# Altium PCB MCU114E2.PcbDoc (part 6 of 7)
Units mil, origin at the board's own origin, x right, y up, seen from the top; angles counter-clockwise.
Board outline 4153.94 x 2313.28 mil, 8 copper layers (Top Layer, GND 2, Signal Layer 3, Power 4, Power 5, Signal Layer 6, GND 7, Bottom), stack 61.2 mil thick; 444 components, 418 nets, 1811 pads, 981 vias.
Unrouted connection lines stored in the file: 3.
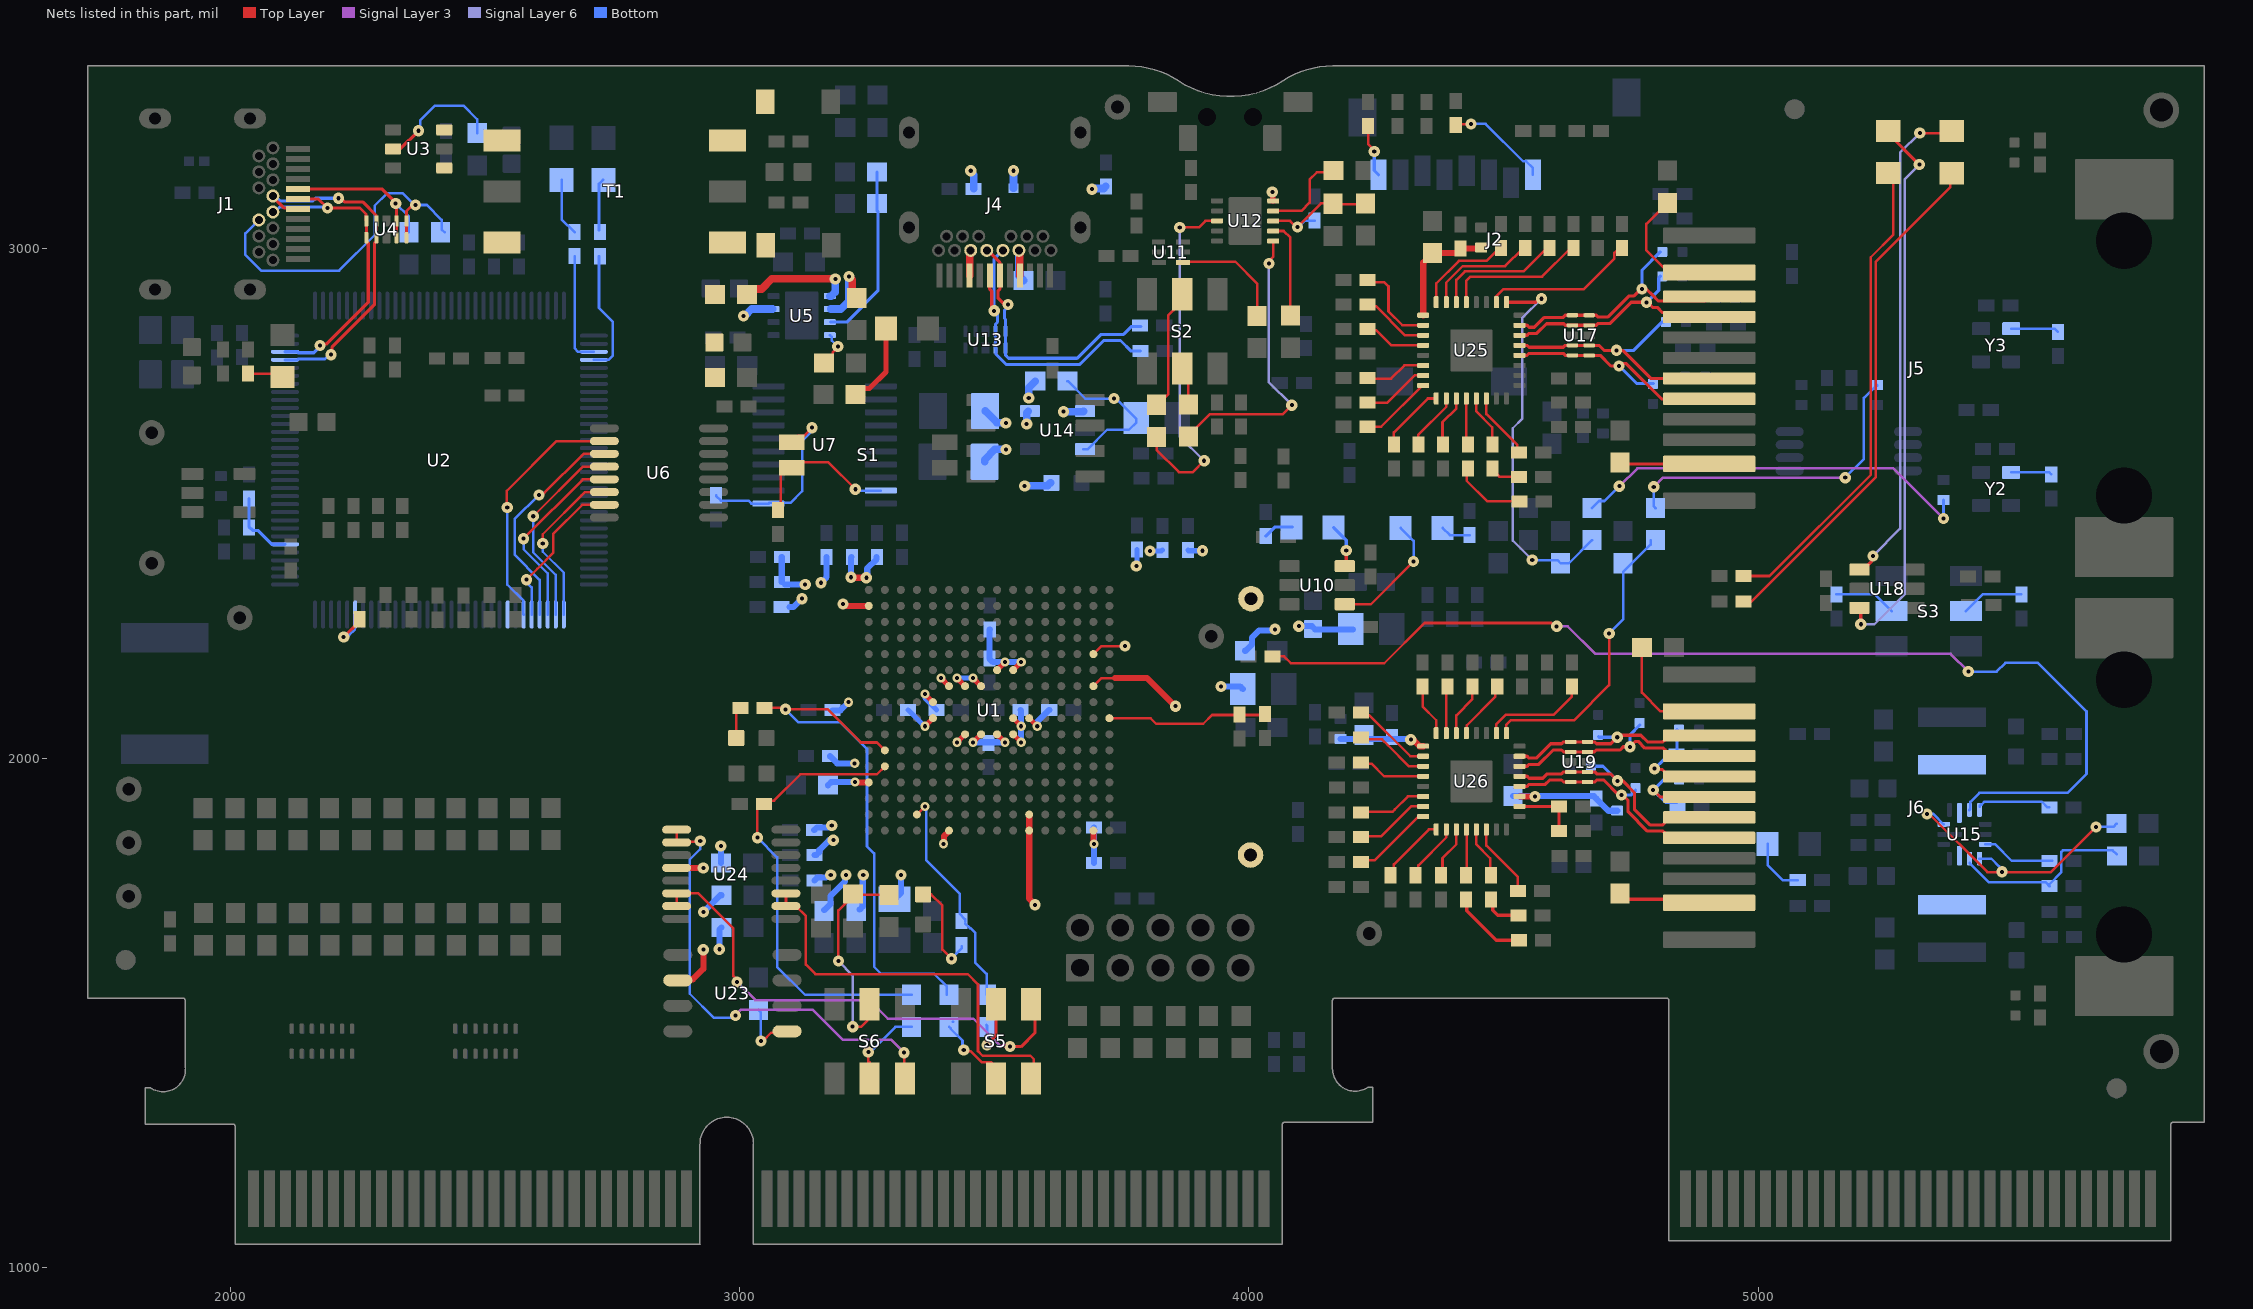
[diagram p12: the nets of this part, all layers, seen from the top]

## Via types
v1: diameter 22, hole 8, Top Layer to Bottom, tented both sides, 810 vias
v2: diameter 18, hole 8, Top Layer to Bottom, tented both sides, 153 vias
v3: diameter 19.68, hole 7.87, Top Layer to Bottom, tented both sides, 10 vias
v4: diameter 19.68, hole 7.87, Top Layer to Bottom, tented bottom, 4 vias
v5: diameter 19.68, hole 7.87, Top Layer to Bottom, tented top, 4 vias

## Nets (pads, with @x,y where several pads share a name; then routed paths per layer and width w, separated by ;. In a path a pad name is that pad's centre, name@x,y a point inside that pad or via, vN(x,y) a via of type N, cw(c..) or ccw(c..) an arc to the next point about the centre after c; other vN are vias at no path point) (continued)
NetC99_1: C99.1 C100.1 R134.1 U25.17 | length 228.9
  Top Layer w12: U25.17@4341.95,2869.58 4341.95,2972.9 4359.83,2990.79 C99.1@4359.83,2991.77 4409.02,2991.77 4414.83,2997.58 C100.1@4414.83,3000.65 4448.05,3000.65 R134.1@4451.99,3004.58
NetC102_2: C102.2 C104.2 J6.5 | length 234.3
  Top Layer w6.25: v1@4797,1981 4800.01,1977.99 4811.04,1977.99 4824.76,1964.27 J6.5@4921.83,1964.27
  Bottom w6.25: v1(4795.94,1979.46) 4814.8,1998.31 4830.69,1998.31 C104.2@4839.38,2007 ; C104.2@4840.44,2008.54 C102.2@4840.44,2056.26
NetC105_1: C105.1 C106.1 U26.2 | length 125.7
  Top Layer w6.1: U26.2@4530.92,1905.47 C106.1@4608.81,1905.47 C105.1@4608.81,1857.69
NetC111_2: C111.2 C112.2 J6.6 | length 247.7
  Top Layer w6.25: v1(4793.44,1937.5) 4806.83,1924.11 J6.6@4921.83,1924.11
  Bottom w6.25: C112.2@4840.44,1913.11 4817.83,1913.11 v1(4793.44,1937.5) 4816.76,1960.83 C111.2@4840.44,1960.83
NetC113_1: C113.1 C114.2 R166.2 U26.3 | length 247.4
  Top Layer w12: U26.3@4530.92,1925.16 4531.4,1924.69 v1(4561.44,1924.69)
  Bottom w12: C113.1@4518,1925.5 4676.95,1925.5 C114.2@4681.65,1920.81 4705.5,1896.95 R166.2@4722.83,1896.95
NetC115_1: C115.1 C116.2 R168.1 U26.17 | length 167.8
  Top Layer w12: v1(4317.67,2036.43) 4320.68,2033.42 4325.22,2033.42 4335.06,2023.58 U26.17@4341.95,2023.58
  Bottom w12: R168.1@4179.99,2037.69 4316.41,2037.69 v1(4317.67,2036.43)
NetC118_2: C118.2 R200.1 | length 203.2
  Top Layer w5: C118.2@3354.6,1732.73 3376.1,1732.73 3397.95,1710.89 3397.95,1624.47 v1(3415.83,1606.58)
  Bottom w5: v1@3410.83,1602.27 3411.39,1602.27 3435.83,1626.71 R200.1@3435.83,1630.65
NetC119_2: C119.2 R201.1 | length 66.9
  Top Layer w5: C119.2@2993.5,2039.58 2993.5,2096.56 R201.1@3000.54,2103.6
NetC121_1: C121.1 U23.5 | length 122.5
  Top Layer w5: v1(3042,1445) 3046,1445 3062.12,1461.12 3090.4,1461.12 U23.5@3093.28,1464
  Bottom w5: C121.1@3036.87,1506.19 3042,1501.06 v1(3042,1445)
NetC122_1: C122.1 R57.1 S6.5 | length 437.6
  Top Layer w5: v1(3194,1601.73) 3194,1701.44 3224.47,1731.91 C122.1@3281.83,1731.91 ; v1(3222,1473) 3239,1473 3250.28,1484.28 3250.28,1515.16 S6.5@3255.47,1520.35 ; R57.1@3222.97,1722.99 R57.1@3224.47,1721.5 ; C122.1@3281.58,1735.12 3281.83,1734.86 C122.1@3281.83,1731.91 ; C122.1@3289,1721.5 3281.83,1728.67 C122.1@3281.83,1731.91 ; C122.1@3289,1731.91 C122.1@3281.83,1731.91
  Signal Layer 6 w5: v1(3194,1601.73) 3222,1573.73 v1(3222,1473)
NetD1:A_2: D1:A.2 T1.1
NetD1_2: D1.2 R14.2 | length 70.8
  Top Layer w5: R14.2@2034.87,2755.06 2096.16,2755.06 D1.2@2102.87,2748.35
NetD2:A_2: D2:A.2 T1.3
NetD2_2: D2.2 R21.1 | length 163.4
  Top Layer w10: R21.1@3227.5,2714.07 3239.51,2726.08 3255.08,2726.08 3287.27,2758.27 D2.2@3287.27,2843.6
NetD3_1: D3.1 U10.6 | length 86.2
  Top Layer w6.25: U10.6@4190.87,2376.69 v1(4190.87,2407.69)
  Bottom w6.25: D3.1@4166.21,2452.69 4190.87,2428.02 v1(4190.87,2407.69)
NetD3_2: D3.2 R34.2 | length 59.3
  Bottom w6.25: R34.2@4032.87,2436.06 4050.49,2453.69 D3.2@4084.87,2453.69
NetD4_1: D4.1 U10.4 | length 246.5
  Top Layer w5: U10.4@4188.01,2302.28 4239.28,2302.28 v1(4323,2386)
  Bottom w5: D4.1@4297.49,2452.27 4323,2426.76 v1(4323,2386)
NetD4_2: D4.2 R35.2 | length 58.6
  Bottom w5: D4.2@4380.17,2452.27 4394.37,2438.06 R35.2@4432.87,2438.06
NetD5_1: D5.1 R8.1 | length 113.1
  Bottom w5: D5.1@2650.87,3135.35 2650.87,3057.91 R8.1@2676.09,3032.69
NetD6_1: D6.1 R9.1 | length 101.9
  Bottom w5: R9.1@2724.09,3036.63 2724.09,3127.57 D6.1@2731.87,3135.35
NetD7_2: D7.2 R94.1 | length 112.9
  Bottom w5: D7.2@5018.1,1831.69 5018.1,1790.02 5047.44,1760.69 R94.1@5077.15,1760.69
NetD8_1: D8.1 U18.6 | length 1090.4
  Top Layer w6.25: U18.6@5198.3,2295.28 5201,2292.59 v1(5201,2263) ; D8.1@5254.83,3231.61 5254.83,3226.27 v1(5315.83,3165.27)
  Signal Layer 6 w5: v1(5201,2263) 5227.56,2263 5287.33,2322.77 5287.33,3136.77 v1(5315.83,3165.27)
NetD8_2: D8.2 R137.1 | length 946.9
  Top Layer w5: R137.1@4971.06,2357.69 5021.75,2357.69 5220.44,2556.37 5220.44,2983.44 5265,3028 5265,3138.76 D8.2@5254.83,3148.93
NetD9_1: D9.1 U18.4 | length 975.1
  Top Layer w5: v1(5316.83,3227.27) 5375.68,3227.27 D9.1@5379.44,3231.02
  Top Layer w6.25: U18.4@5198.3,2370.09 5206.18,2370.09 5221.82,2385.73 5221.82,2394.25 v1(5224.83,2397.27)
  Signal Layer 6 w5: v1(5224.83,2397.27) 5278.33,2450.77 5278.33,3188.77 v1(5316.83,3227.27)
NetD9_2: D9.2 R138.2 | length 1019.3
  Top Layer w5: R138.2@4970.49,2307.69 4986.25,2307.69 5230.69,2552.12 5230.69,2974.69 5376.98,3120.98 5376.98,3145.89 D9.2@5379.44,3148.35
NetJ2_1: J2.1 R37.1 | length 201.7
  Top Layer w5: R37.1@4405.83,3242.65 4408.04,3244.85 v1(4435.79,3244.85)
  Bottom w5: v1(4435.79,3244.85) 4436.21,3245.27 4464.56,3245.27 4537.96,3171.87 4544.12,3171.87 4557.37,3158.62 J2.1@4557.37,3145.39
NetJ2_8: J2.8 R43.2 | length 104.1
  Top Layer w5: R43.2@4233.87,3241.06 4233.87,3205.47 4245.83,3193.51 v1(4245.83,3191.27)
  Bottom w6.25: v1(4245.83,3191.27) 4245.83,3153.78 J2.8@4254.22,3145.39
NetJ5_2: J5.2 R135.2 | length 251.8
  Top Layer w5: R135.2@4821.39,3090.33 4780,3048.94 4780,2997 4823.52,2953.48 J5.2@4903.31,2953.48
NetJ5_11: J5.11 R132.2 | length 179.1
  Top Layer w6.25: R132.2@4726.64,2592.39 R132.2@4728.94,2594.69 ; R132.2@4728.44,2580.19 4730.73,2577.89 J5.11@4903.31,2577.89
NetJ6_2: J6.2 R169.2 | length 235.8
  Top Layer w5: R169.2@4771.34,2217.27 4771.34,2128.66 4808.17,2091.83 J6.2@4903.31,2091.83
NetJ6_11: J6.11 R167.2 | length 182.3
  Top Layer w6.25: R167.2@4728.44,1734.19 4739.36,1723.27 4896.27,1723.27 J6.11@4903.31,1716.24
NetL1_1: L1.1 U15.6
NetL2_1: L2.1 U15.12
NetR1_1: R1.1 S1.1 U7.1 | length 370.9
  Top Layer w5: S1.1@3102.35,2620.26 3114.81,2632.72 3126.12,2632.72 v1(3142.28,2648.89)
  Bottom w5: R1.1@2954.11,2516.2 2954.11,2514.81 2963.42,2505.5 3017.5,2505.5 3023.16,2499.84 U7.1@3056.76,2499.84 3058.13,2501.21 3099.84,2501.21 3123,2524.37 3123,2622.95 3142.28,2642.23 v1(3142.28,2648.89)
NetR8_2: R8.2 U2.3 | length 221.4
  Bottom w5: R8.2@2676.09,2985.44 2676.09,2804.91 2683.14,2797.86 U2.3@2714,2797.86
NetR9_2: R9.2 U2.4 | length 246.7
  Bottom w5: U2.4@2714,2782.11 2742.4,2782.11 2751.3,2791 2751.3,2856.7 2724.09,2883.91 R9.2@2724.09,2985.44
NetR10_1: R10.1 R11.2 U2.70 | length 140.6
  Bottom w6.25: R10.1@2036.87,2510.06 2036.87,2454.69 2044.4,2447.16 2054.4,2447.16 2081.34,2420.21 2107.39,2420.21 U2.70@2107.7,2419.9
NetR12_2: R12.2 U2.59 | length 105.5
  Top Layer w6.25: v1(2222.83,2238.27) 2223.48,2238.27 2254.09,2268.89 R12.2@2254.09,2272.82
  Bottom w5: v1(2222.83,2238.27) 2226.08,2241.52 2233.65,2241.52 2244.97,2252.84 2244.97,2281.58 U2.59@2245.49,2282.11
NetR18_1: R18.1 U3.5 | length 248.7
  Top Layer w6.25: U3.5@2319.9,3196.07 2334.25,3196.07 v1(2369.87,3231.69)
  Bottom w5: v1(2369.87,3231.69) 2372.89,3234.7 2372.89,3251.86 2402.03,3281 2458.16,3281 2485.09,3254.07 R18.1@2485.09,3226.94
NetR19_1: R19.1 U5.1 | length 226.3
  Top Layer w15: R19.1@3014.5,2910 3025.59,2921.09 3043.61,2921.09 3063.52,2941 v1(3188,2941)
  Bottom w15: U5.1@3177.12,2907.19 3179.83,2907.19 3188,2915.35 v1(3188,2941)
NetR24_1: R24.1 R26.2 U5.3 | length 352
  Bottom w6.25: U5.3@3179.12,2856.2 3210.23,2856.2 3271.5,2917.47 3271.5,3073.46 3269.53,3075.43 R24.1@3269.53,3150.9
NetR25_2: R25.2 U5.4 | length 73.1
  Top Layer w5: R25.2@3165.5,2776 3166.49,2776 3182.69,2792.2 3182.69,2796.68 3192.83,2806.82 v1(3192.83,2808.11)
  Bottom w5: U5.4@3177.12,2830.42 3177.59,2830.42 3180.99,2827.01 3180.99,2819.94 v1(3192.83,2808.11)
NetR27_2: R27.2 U5.2 | length 140.2
  Top Layer w15: v1(3214.92,2945.6) 3221,2939.52 3221,2910.5 R27.2@3230,2901.5
  Bottom w15: U5.2@3179.12,2881.8 3198.35,2881.8 3214.92,2898.37 v1(3214.92,2945.6)
NetR33_1: R33.1 S2.2 | length 237.8
  Top Layer w5: R33.1@3820.44,2693.2 3841.81,2714.58 3841.81,2869.81 3851.81,2879.81 3851.81,2893.65 S2.2@3869,2910.83
NetR33_2: R33.2 U12.3 | length 702.6
  Top Layer w5: R33.2@3818.8,2630.9 3818.8,2605.18 3862.21,2561.77 3889.77,2561.77 v1(3912,2584) ; v1(3864,3042) 3901.61,3042 3914.29,3054.69 U12.3@3937.32,3054.69
  Signal Layer 6 w5: v1(3864,3042) 3864,2632 v1(3912,2584)
NetR44_2: R44.2 U11.4 | length 227.9
  Top Layer w5: U11.4@3870.41,2973.58 3870.41,2974.77 3973,2974.77 4016,2931.77 R44.2@4016,2868.5
NetR46_2: R46.2 R48.2 U1.J16 | length 317.2
  Top Layer w5: U1.J16@3726.04,2078.54 3806.73,2078.54 3817.52,2067.75 3910.17,2067.75 3927.33,2084.91 4029.29,2084.91 R46.2@4031,2086.62
NetR49_2: R49.2 U12.9 | length 179.7
  Top Layer w5: U12.9@4047.55,3074.37 4102.83,3074.37 4119,3090.54 4119,3135.77 4133.5,3150.27 R49.2@4169.34,3150.27
NetR52_1: R52.1 U12.6 | length 574.3
  Top Layer w5: R52.1@3881.87,2631.19 3881.87,2634.23 3922.64,2675 4066,2675 v1(4084,2693) ; v1(4039,2971) 4039,2975.6 4047.55,2984.15 U12.6@4047.55,3015.32
  Signal Layer 6 w5: v1(4039,2971) 4038.71,2970.71 4038.71,2738.29 v1(4084,2693)
NetR52_2: R52.2 S2.5 | length 75.6
  Top Layer w5: S2.5@3869,2765.17 3881,2753.17 R52.2@3881,2694.5
NetR53_1: R53.1 U15.4 U15.10 | length 567
  Top Layer w5: v1@5324.44,1890.69 v1(5330.83,1890.69) 5335.31,1890.69 5449.47,1776.53 5574.09,1776.53 v1(5662.83,1865.27)
  Bottom w5: v1(5330.83,1890.69) 5343.27,1890.69 U15.10@5363.59,1870.37 ; U15.4@5433.96,1802.95 5457.01,1802.95 5472.4,1787.56 5472.4,1787.2 5483.07,1776.53 v1@5483.44,1776.53 ; v1(5662.83,1865.27) 5696.61,1865.27 R53.1@5702.94,1871.6
  other v1: 5478,1777
NetR55_2: R55.2 R61.1 R78.2 U12.8 | length 245.2
  Top Layer w5: U12.8@4047.55,3054.69 4080.52,3054.69 4092.21,3043 v1(4095,3043) 4141.06,3089.06 R78.2@4166.72,3089.06 ; R78.2@4168.13,3087.76 R55.2@4231.13,3087.76
  Bottom w5: v1(4095,3043) 4097.79,3043 4109.48,3054.69 4128.31,3054.69 R61.1@4129,3055.38
NetR58_1: R58.1 U25.23 | length 132
  Top Layer w5: R58.1@4232.06,2698.02 4271.77,2698.02 4325.22,2751.47 U25.23@4341.95,2751.47
NetR62_2: R62.2 S3.2 | length 122.4
  Bottom w5: S3.2@5407.27,2288.69 5440.21,2321.62 R62.2@5516,2321.62
NetR63_2: R63.2 S3.5 | length 122.3
  Bottom w5: R63.2@5152.94,2321.62 5228.66,2321.62 S3.5@5261.6,2288.69
NetR69_1: R69.1 Y2.1 | length 80.3
  Bottom w5: Y2.1@5496.13,2561.17 5570.93,2561.17 R69.1@5574.83,2557.27
NetR76_1: R76.1 Y3.1 | length 94.3
  Bottom w5: Y3.1@5496.13,2843.17 5581.56,2843.17 R76.1@5587.83,2836.89
NetR82_1: R82.1 U15.13 | length 2112.5
  Top Layer w5: R82.1@4046.45,2200 4068.91,2200 4082.41,2186.5 4265.5,2186.5 4344.5,2265.5 4592.9,2265.5 4599.4,2259 v1(4604,2259)
  Signal Layer 3 w5: v1(4604,2259) 4625.75,2259 4679.75,2205 4956.35,2205 4956.58,2204.77 4971.08,2204.77 4971.31,2205 5377,2205 v1(5412,2170)
  Bottom w5: v1(5412,2170) 5467.6,2170 5484.91,2187.31 5548.69,2187.31 5644.03,2091.97 5644.03,1969.03 5607,1932 5433.74,1932 5416.05,1914.31 5416.05,1900.19 U15.13@5414.28,1898.42
NetR83_1: R83.1 U25.27 | length 101.1
  Top Layer w5: R83.1@4379.8,2616.31 4379.8,2659.8 4406.91,2686.91 U25.27@4406.91,2706.2
NetR84_1: R84.1 U25.26 | length 112.7
  Top Layer w5: R84.1@4332.12,2616.31 4332.12,2634.47 4387.22,2689.58 U25.26@4387.22,2706.2
NetR86_1: R86.1 U25.25 | length 133.9
  Top Layer w5: R86.1@4284.44,2616.31 4284.44,2639.44 4351.2,2706.2 U25.25@4367.54,2706.2
NetR87_1: R87.1 U25.24 | length 143.5
  Top Layer w5: R87.1@4232.06,2650.69 4259.44,2650.69 4340.54,2731.79 U25.24@4341.95,2731.79
NetR91_1: R91.1 U26.23 | length 147.2
  Top Layer w5: R91.1@4218.95,1847.13 4259.88,1847.13 4264.77,1852.02 4318.22,1905.47 U26.23@4341.95,1905.47
NetR92_1: R92.1 U26.27 | length 101.1
  Top Layer w5: R92.1@4379.8,1770.31 4379.8,1804.05 4406.91,1831.16 U26.27@4406.91,1860.2
NetR97_1: R97.1 U15.3 | length 145.2
  Bottom w5: U15.3@5445.28,1831 5465,1831 5497.31,1798.69 R97.1@5577.1,1798.69
NetR100_1: R100.1 S1.2 U7.19 | length 347.1
  Top Layer w5: R100.1@3075,2487.62 3081.13,2493.75 3081.13,2557.8 3082.41,2559.09 3084.1,2559.09 3095.27,2570.26 S1.2@3102.35,2570.26 3097.84,2570.26 3096.56,2568.98 S1.2@3085.38,2557.8 ; S1.2@3082.76,2560.59 3093.85,2571.69 3103.02,2580.86 3174.34,2580.86 v1(3227.21,2527.99)
  Bottom w5: v1(3227.21,2527.99) 3229.77,2525.43 U7.19@3277.24,2525.43
NetR103_1: R103.1 R104.2 U15.5 | length 361.6
  Bottom w5: U15.5@5414.5,1794.37 5451.86,1757 5563.38,1757 5569.44,1750.94 R103.1@5571.38,1749 ; R103.1@5571.19,1752.69 5594.81,1776.31 5594.81,1816.32 5597.74,1819.25 5695.37,1819.25 R104.2@5702.94,1811.69
NetR109_2: R109.2 U25.10 | length 297.5
  Top Layer w5: U25.10@4485.65,2895.17 4485.65,2907.09 4498.83,2920.27 4656.83,2920.27 4717.36,2980.8 4717.36,2992.18 R109.2@4725.83,3000.65
NetR110_1: R110.1 U26.26 | length 112.6
  Top Layer w5: R110.1@4332.44,1770.31 4332.44,1789.69 4387.22,1844.47 U26.26@4387.22,1860.2
NetR114_2: R114.2 U25.19 | length 133.6
  Top Layer w5: R114.2@4232.06,2887.35 4249.36,2887.35 4306.5,2830.21 U25.19@4341.95,2830.21
NetR115_2: R115.2 U25.18 | length 173.7
  Top Layer w5: R115.2@4232.06,2934.69 4265.44,2934.69 4273.87,2926.25 4273.87,2877.25 4301.22,2849.9 U25.18@4341.95,2849.9
NetR116_2: R116.2 U25.15 | length 216.5
  Top Layer w5: U25.15@4387.22,2895.17 4387.22,2933.66 4419.58,2966.02 4502.86,2966.02 R116.2@4537.49,3000.65
NetR117_2: R117.2 U25.14 | length 246.4
  Top Layer w5: U25.14@4406.91,2895.17 4406.91,2938.85 4423.83,2955.77 4539.18,2955.77 R117.2@4584.06,3000.65
NetR118_2: R118.2 U25.13 | length 272.5
  Top Layer w5: U25.13@4426.59,2895.17 4426.59,2937.56 4434.55,2945.52 4575.49,2945.52 R118.2@4630.62,3000.65
NetR119_2: R119.2 U25.20 | length 122.1
  Top Layer w5: R119.2@4232.06,2840.02 4249.94,2840.02 4279.44,2810.53 U25.20@4341.95,2810.53
NetR120_2: R120.2 U25.22 | length 120.6
  Top Layer w5: R120.2@4232.06,2745.35 4279.1,2745.35 4304.91,2771.16 U25.22@4341.95,2771.16
NetR121_1: R121.1 R123.2 | length 141.3
  Top Layer w5: R121.1@4427.48,2569.06 4427.48,2544.65 4467.44,2504.69 R123.2@4527.81,2504.69
NetR121_2: R121.2 U25.28 | length 90.3
  Top Layer w5: U25.28@4426.59,2706.2 4426.59,2617.19 R121.2@4427.48,2616.31
NetR122_1: R122.1 R124.2 | length 58.4
  Top Layer w5: R122.1@4475.16,2569.06 4491.53,2552.69 R124.2@4526.81,2552.69
NetR122_2: R122.2 U25.29 | length 103.7
  Top Layer w5: U25.29@4446.28,2706.2 4446.28,2680.84 4477.44,2649.69 4477.44,2618.59 R122.2@4475.16,2616.31
NetR125_2: R125.2 U25.30 | length 130.7
  Top Layer w5: U25.30@4465.96,2706.2 4465.96,2675.56 4519.19,2622.34 4526.81,2614.71 R125.2@4526.81,2600.69
NetR126_2: R126.2 U25.16 | length 188.6
  Top Layer w5: U25.16@4367.54,2895.17 4367.54,2931.98 4411.83,2976.27 4466.54,2976.27 R126.2@4490.92,3000.65
NetR143_2: R143.2 U26.10 | length 207.9
  Top Layer w5: U26.10@4485.65,2049.17 4485.65,2067.09 4503.83,2085.27 4597.83,2085.27 4633.83,2121.27 R143.2@4633.83,2140.65
NetR144_1: R144.1 U26.25 | length 132.9
  Top Layer w5: R144.1@4284.44,1770.31 4284.52,1770.39 4284.52,1791.77 4352.95,1860.2 U26.25@4367.54,1860.2
NetR148_2: R148.2 U26.19 | length 144.8
  Top Layer w5: R148.2@4218.95,2036.84 4261.28,2036.84 4272.34,2025.78 4313.91,1984.21 U26.19@4341.95,1984.21
NetR149_2: R149.2 U26.18 | length 156.3
  Top Layer w5: R149.2@4218.95,2084.27 4236.48,2084.27 4316.85,2003.9 U26.18@4341.95,2003.9
NetR150_2: R150.2 U26.15 | length 92.5
  Top Layer w5: U26.15@4387.22,2049.17 4387.22,2138.2 R150.2@4389.66,2140.65
NetR151_1: R151.1 U26.30 | length 145.1
  Top Layer w5: U26.30@4465.96,1859.2 4465.96,1828.6 4527.81,1766.75 R151.1@4527.81,1739.69
NetR152_2: R152.2 U26.14 | length 104.6
  Top Layer w5: U26.14@4406.91,2049.17 4406.91,2084.27 4438.5,2115.86 R152.2@4438.5,2140.65
NetR153_2: R153.2 U26.13 | length 116.6
  Top Layer w5: U26.13@4426.59,2049.17 4427.46,2050.04 4427.46,2064.49 4483.29,2120.33 4483.29,2136.61 R153.2@4487.33,2140.65
NetR154_2: R154.2 U26.20 | length 133.3
  Top Layer w5: R154.2@4218.95,1989.41 4240.59,1989.41 4265.31,1964.69 4341.79,1964.69 U26.20@4341.95,1964.53
NetR155_2: R155.2 U26.22 | length 135.7
  Top Layer w5: R155.2@4218.95,1894.55 4281.3,1894.55 4286.1,1899.35 4311.91,1925.16 U26.22@4341.95,1925.16
NetR156_1: R156.1 R159.2 | length 148.8
  Top Layer w6.25: R156.1@4427.48,1723.06 4427.48,1700.65 4485.44,1642.69 R159.2@4529.81,1642.69
NetR156_2: R156.2 U26.28 | length 90.3
  Top Layer w5: U26.28@4426.59,1860.2 4427.48,1859.31 R156.2@4427.48,1770.31
NetR157_1: R157.1 R160.2 | length 77.3
  Top Layer w6.25: R157.1@4475.16,1723.06 4478.52,1719.7 4478.52,1701.6 4488.44,1691.69 R160.2@4528.81,1691.69
NetR157_2: R157.2 U26.29 | length 101.9
  Top Layer w5: U26.29@4446.28,1860.2 4446.28,1830.84 4473.44,1803.69 4473.44,1772.03 R157.2@4475.16,1770.31
NetR158_2: R158.2 U26.16 | length 102.5
  Top Layer w5: R158.2@4340.83,2140.65 4340.83,2101.29 4367.54,2074.58 U26.16@4367.54,2049.17
NetR171_2: R171.2 U15.14 | length 147
  Bottom w5: U15.14@5434.03,1904.9 5434.03,1906.85 5436.38,1909.21 5438.34,1909.21 5443.96,1914.83 5556.11,1914.83 5567.25,1903.69 R171.2@5571.19,1903.69
NetR196_1: R196.1 S6.2 | length 184.2
  Top Layer w5: v1(3252.76,1423.32) 3252.76,1377.38 3255.47,1374.68 3255.47,1403.53
  Bottom w5: v1(3252.76,1423.32) 3256.61,1423.32 3306.06,1472.77 R196.1@3337.83,1472.77
NetR196_2: R196.2 R199.2 U1.M2 | length 897.6
  Top Layer w5: v1(3035,1844) 3035,1900.69 3044.31,1910 R199.2@3047.62,1910 3054.56,1916.94 3067.94,1916.94 3119.53,1968.53 3269.58,1968.53 U1.M2@3285.09,1984.05
  Bottom w5: v1(3035,1844) 3073.88,1805.12 3073.88,1590.42 3128.54,1535.76 R196.2@3337.83,1535.76
NetR197_1: R197.1 S5.5 | length 132.7
  Top Layer w6.1: v1(3485.58,1437.27) 3503.37,1455.07 3503.37,1512.66 S5.5@3511.06,1520.35
  Bottom w6.1: R197.1@3484.83,1476.07 3485.58,1475.32 v1(3485.58,1437.27)
NetR197_2: R197.2 R200.2 U1.R4 | length 438.6
  Top Layer w5: U1.R4@3348.09,1889.56 v2(3363.83,1905.31)
  Bottom w5: v2(3363.83,1905.31) 3366.08,1903.06 3366.08,1800.02 3431.83,1734.27 3431.83,1694.83 3442.83,1683.83 R200.2@3442.83,1679.89 ; R200.2@3442.83,1675.95 3452.14,1666.64 3453.15,1666.64 3462.83,1656.96 3462.83,1611.17 3462.83,1598.44 3484.83,1576.44 R197.2@3484.83,1535.76
NetR198_1: R198.1 S5.2 | length 157.6
  Top Layer w5: v1(3440,1427) 3442.27,1424.73 3453.89,1424.73 3474.95,1403.67 3493.87,1403.67 3511.06,1386.49 S5.2@3511.06,1374.68
  Bottom w5: R198.1@3411.33,1472.77 3414.1,1470 3414.1,1469.02 3437.62,1445.5 3437.62,1429.38 v1(3440,1427) ; R198.1@3418.76,1482.6 R198.1@3418.96,1482.39
NetR198_2: R198.2 R201.2 U1.L2 | length 1071.6
  Top Layer w5: R201.2@3048.78,2098.75 3086.59,2098.75 3089.33,2096 3173.16,2096 3238.24,2030.92 3269.72,2030.92 U1.L2@3285.09,2015.55
  Bottom w5: v1(3090,2096) 3115.73,2070.27 3198.08,2070.27 3250.12,2018.23 3250.12,1826.88 3264,1813 3264,1590.74 3277.74,1577 3382.07,1577 3406.83,1552.24 R198.2@3406.83,1535.76
NetR203_1: R203.1 U26.24 | length 158.7
  Top Layer w5: R203.1@4218.95,1799.7 4246.45,1799.7 4272.42,1825.67 4332.54,1885.79 U26.24@4341.95,1885.79
NetR212_2: R212.2 U12.7 | length 192.1
  Top Layer w5: U12.7@4047.55,3035 4068,3035 4081.04,3021.96 R212.2@4081.04,2868.78
NetS5_3: S5.3 U24.10 U24.11 | length 801.2
  Top Layer w5: U24.11@3091.11,1734.77 U24.10@3091.11,1709.77 3110.28,1709.77 3129.98,1690.07 3129.98,1595.02 3148.66,1576.34 3447.95,1576.34 3468.08,1556.22 3468.08,1424.92 3477,1416 3571,1416 3577.86,1409.14 S5.3@3577.86,1376.77
NetS5_6: S5.6 U24.6 U24.7 | length 983.8
  Top Layer w5: U24.7@2876.55,1709.77 U24.6@2876.55,1734.77 2919.33,1734.77 2988,1666.1 2988,1572.43 2995,1565.43 v1(2995,1561) ; U24.7@2877.55,1706.77 U24.7@2877.55,1709.77
  Top Layer w6.25: v1(3531,1434) 3552.69,1434 3579.96,1461.27 S5.6@3579.96,1520.35
  Signal Layer 3 w5: v1(2995,1561) 3031,1525 3255,1525 3291.37,1488.63 3458.97,1488.63 3512.5,1435.09 3529.91,1435.09 v1(3531,1434)
NetS6_3: S6.3 U24.1 U24.2 | length 915.1
  Top Layer w5: U24.1@2876.55,1859.77 U24.2@2876.55,1834.77 2877.8,1836.02 2921.56,1836.02 v1(2922.81,1837.27) ; S6.3@3316.69,1372.03 3323,1378.34 v1(3323,1422)
  Signal Layer 3 w5: v1(2991.83,1495.27) 3003.12,1506.56 3136.34,1506.56 3136.37,1506.52 3143.48,1506.52 3203,1447 3298,1447 v1(3323,1422)
  Bottom w5: v1(2922.81,1837.27) 2922.81,1821.66 2902.24,1801.1 2902.24,1537.74 2949.74,1490.24 2982.2,1490.24 2987.23,1495.27 v1(2991.83,1495.27)
NetT1_4: T1.4 U3.3
NetT1_6: T1.6 U3.1
PHY0_25MHZ_CLK: R60.2 R67.2 | length 799.4
  Signal Layer 3 w5.2: v1(4727,2534) 4762.17,2569.17 5264.95,2569.17 v1(5363.44,2470.69)
  Bottom w5.2: R60.2@4673.45,2491.17 4687.12,2504.85 4697.85,2504.85 v1(4727,2534) ; v1(5363.44,2470.69) R67.2@5363.44,2507
PHY0_CLK: R59.2 R60.1 U25.9 | length 762.5
  Top Layer w6.25: U25.9@4505.33,2895.17 4562.91,2895.17 4569.74,2902 v1(4574,2902)
  Signal Layer 6 w5: v1(4556,2389) 4517.71,2427.29 4517.71,2647.78 4536.76,2666.83 4536.76,2864.76 v1(4574,2902)
  Bottom w5: v1(4556,2389) 4605.6,2389 R59.2@4611.88,2382.72 4627.99,2382.72 R60.1@4673.45,2428.17
PHY0_RD_N: C93.1 J5.8 U17.5 U17.6 U25.4 | length 495.2
  Top Layer w6.2: U25.4@4530.92,2790.84 4545.73,2790.84 4549.58,2794.69 4616.9,2794.69 4620.74,2790.84 U17.5@4634.86,2790.84 U17.6@4667.74,2790.84 4689.56,2790.84 4710.42,2769.98 v1(4726.44,2769.98) ; v1@4726.12,2773 4727.8,2774.69 4740.42,2774.69 4809.65,2705.45 J5.8@4903.31,2705.45
  Bottom w6.2: v1(4726.44,2769.98) 4760.9,2735.52 C93.1@4793.45,2735.52
PHY0_RD_P: C94.1 J5.7 U17.4 U17.7 U25.5 | length 518.3
  Top Layer w6.2: U25.5@4530.92,2810.53 4545.73,2810.53 4549.58,2806.69 4616.9,2806.69 4620.74,2810.53 U17.4@4634.86,2810.53 U17.7@4667.74,2810.53 4687.13,2810.53 4696.97,2800.69 v1(4721.44,2800.69) 4733.49,2800.69 4788.57,2745.61 J5.7@4903.31,2745.61
  Bottom w6.2: v1(4721.44,2800.69) 4755.13,2800.69 4801.73,2847.29 4810.44,2856 C94.1@4814.38,2856
PHY0_TD_N: C91.1 J5.4 U17.2 U17.9 U25.6 | length 475.7
  Top Layer w6.2: U25.6@4530.92,2830.21 4545.83,2830.21 4549.58,2833.96 4565.05,2833.96 4583.9,2852.8 4617.74,2852.8 4620.64,2849.9 U17.2@4634.86,2849.9 U17.9@4667.74,2849.9 4681.96,2849.9 4685.7,2853.64 4709.05,2853.64 4750.37,2894.95 v1(4780.55,2894.95) 4782.13,2894.95 4792.09,2885 4801.33,2885 4811.34,2874.99 4894.4,2874.99 J5.4@4903.31,2866.08
  Bottom w6.2: v1(4780.55,2894.95) 4804.28,2918.68 4804.28,2942.9 C91.1@4807.38,2946
PHY0_TD_P: C92.1 J5.3 U17.1 U17.10 U25.7 | length 518.4
  Top Layer w6.2: U25.7@4530.92,2849.9 4545.83,2849.9 4549.58,2846.16 4560,2846.16 4578.84,2865 4616.06,2865 4620.64,2869.58 U17.1@4634.86,2869.58 U17.10@4667.74,2869.58 4681.96,2869.58 4685.7,2865.84 4704,2865.84 4745.31,2907.15 4755,2907.15 4768.69,2920.84 v1(4771.36,2920.84) 4780.27,2920.84 4792.27,2908.83 4803.78,2897.33 4894.4,2897.33 J5.3@4903.31,2906.24
  Bottom w6.2: v1@4764.89,2914.7 v1@4771.2,2921.01 ; v1(4771.36,2920.84) 4771.36,2957.99 C92.1@4807.38,2994
PHY1_25MHZ_CLK: R66.2 R68.2 | length 635
  Signal Layer 3 w5.2: v1(4794.56,2532.83) 4812.51,2550.77 v1(5170.39,2550.78)
  Bottom w5.2: v1(4794.56,2532.83) 4794.56,2494.43 R66.2@4798,2490.99 ; v1(5170.39,2550.78) 5207,2587.38 5207,2707.09 R68.2@5232.44,2732.53 R68.2@5233.19,2731.77
PHY1_CLK: R64.2 R66.1 U26.9 | length 569.1
  Top Layer w5: U26.9@4505.33,2049.17 4505.33,2066.11 4514.22,2075 4638.56,2075 4707,2143.44 v1(4707,2245)
  Bottom w5: v1(4707,2245) 4734.44,2272.44 4734.44,2365.18 4788.44,2419.18 R66.1@4788.44,2428.17
PHY1_RD_N: C109.1 J6.8 U19.5 U19.6 U26.4 | length 472.6
  Top Layer w6.2: U26.4@4530.92,1944.84 4545.83,1944.84 4549.58,1948.59 4581.84,1948.59 4590.45,1957.19 4613.58,1957.19 4617.33,1953.45 U19.5@4631.55,1953.45 U19.6@4664.42,1953.45 4678.64,1953.45 4682.39,1957.19 4696.33,1957.19 4725.84,1927.69 v1(4731.44,1927.69) 4733.5,1927.69 4744.25,1916.93 4744.25,1894.69 4781.95,1857 4812.22,1857 4815.85,1853.37 4815.85,1852.7 4824.76,1843.8 J6.8@4903.31,1843.8
  Bottom w6.2: v1(4731.44,1927.69) 4749.31,1927.69 C109.1@4759,1937.38
PHY1_RD_P: C110.1 J6.7 U19.4 U19.7 U26.5 | length 509.2
  Top Layer w6.2: U26.5@4530.92,1964.53 4545.83,1964.53 4549.58,1960.79 4576.79,1960.79 4585.39,1969.39 4613.58,1969.39 4617.33,1973.13 U19.4@4631.55,1973.13 U19.7@4664.42,1973.13 4678.64,1973.13 4682.39,1969.39 4709.73,1969.39 v1(4723.44,1955.69) 4733.51,1955.69 4756.45,1932.74 4756.45,1899.75 4787,1869.2 4812.22,1869.2 4815.85,1872.83 4815.85,1875.05 4824.76,1883.95 J6.7@4903.31,1883.95
  Bottom w6.2: C110.1@4674.92,1984.21 4694.91,1984.21 v1(4723.44,1955.69)
PHY1_TD_N: C107.1 J6.4 U19.2 U19.9 U26.6 | length 428.9
  Top Layer w6.2: U26.6@4530.92,1984.21 4545.83,1984.21 4549.58,1987.96 4569.05,1987.96 4597.34,2016.25 4613.58,2016.25 4617.33,2012.5 U19.2@4631.55,2012.5 U19.9@4664.42,2012.5 4664.75,2012.83 4678,2012.83 4681.42,2016.25 4728.58,2016.25 4734.78,2022.44 v1(4748.14,2022.44) 4758.7,2033 4764,2033 4777.2,2019.8 4813.42,2019.8 J6.4@4817.85,2015.37 ; J6.4@4842.4,2004.43 J6.4@4903.31,2004.43
  Bottom w6.2: v1(4748.14,2022.44) 4748.14,2046.36 C107.1@4766.92,2065.15
PHY1_TD_P: C108.1 J6.3 U19.1 U19.10 U26.7 | length 355.1
  Top Layer w6.2: U26.7@4530.92,2003.9 4545.83,2003.9 4549.58,2000.16 4564,2000.16 4592.29,2028.45 4613.58,2028.45 4617.33,2032.19 U19.1@4631.55,2032.19 U19.10@4664.42,2032.19 4664.75,2031.86 4678.75,2031.86 4682.17,2028.45 4710.01,2028.45 v1(4722.83,2041.27) 4726.76,2045.2 4769.05,2045.2 4782.25,2032 4812.22,2032 4815.85,2035.64 4817.22,2037.05 J6.3@4817.85,2037.05
  Bottom w6.2: C108.1@4686.08,2042.65 4687.46,2041.27 v1(4722.83,2041.27)
POWER_SWITCH_OUT: C26.2 R19.2 R20.2 U5.7 | length 62.3
  Bottom w15: v1(3008,2868) 3009.89,2868 3023.79,2881.9 U5.7@3064.57,2881.9
USB-PFLT: R85.1 R90.1 U14.3 | length 298.6
  Bottom w5: R90.1@3643.39,2740.22 3644.37,2740.22 3678.59,2706 3738.6,2706 3778.83,2665.77 3778.83,2659.27 3764.33,2644.77 3721.37,2644.77 3682.88,2606.28 U14.3@3675.01,2606.28
  other v1: 3735,2706
USB_5V0: C46.1 C47.1 R90.2 R93.1 U14.5 | length 199.1
  Bottom w15: C47.1@3481.18,2582 3481.18,2586.2 3501.24,2606.26 v1(3523.17,2606.26) ; C46.1@3482.05,2681.69 3505.45,2658.29 v1(3522.69,2658.29) ; v1(3563.55,2655.99) 3563.55,2677.9 U14.5@3566.74,2681.09 ; v1(3567.7,2706.94) 3567.7,2727.53 R90.2@3580.4,2740.22 ; v1(3692,3117) 3693.34,3118.34 3714.84,3118.34 R93.1@3719,3122.5
USB_D_N: J4.A7 J4.B7 R81.1 U13.2 U13.9 | length 598.1
  Top Layer w6.1: J4.A7@3491.16,2947.46 3491.16,2920.79 3494.95,2917 v1@3494.95,2887.17
  Bottom w6.1: J4.B7@3516.75,2997.07 3499.83,2980.15 v1(3499.83,2878.23) 3506.16,2871.89 3506.16,2855.96 3502.37,2852.17 U13.9@3502.37,2838 U13.2@3502.37,2805.13 3503.26,2804.24 3503.26,2792.74 3522.91,2773.09 3667.76,2773.09 3671.31,2776.63 3714.67,2820 3747.77,2820 3768.58,2799.19 R81.1@3787.38,2799.19
USB_D_P: J4.A6 J4.B6 R80.1 U13.1 U13.10 | length 528.5
  Top Layer w6.1: J4.B6@3485.25,2997.07 3487.27,2997.07 3510.84,2973.5 J4.A6@3510.84,2947.46 3510.84,2920.79 3507.05,2917 3507.05,2903.77 3520.37,2890.45 v1(3526.67,2890.45)
  Bottom w6.1: v1(3526.67,2890.45) 3526.67,2886.14 3520.12,2879.59 3520.12,2863.35 3522.06,2861.42 U13.10@3522.06,2838 U13.1@3522.06,2805.13 3522.34,2804.84 3522.34,2790.77 3527.92,2785.19 3662.75,2785.19 3709.66,2832.1 3753.87,2832.1 3768.96,2847.19 R80.1@3787.76,2847.19
VBUS_5V0: C44.1 C45.2 J4.A4 J4.A9 J4.B4 J4.B9 R77.2 R79.2 U14.1 | length 329
  Top Layer w15: J4.A9@3451.79,2947.46 3451.79,2995.1 J4.B4@3453.76,2997.07 ; J4.B9@3548.24,2997.07 3550.21,2995.1 J4.A4@3550.21,2947.46
  Bottom w15: v1(3453.83,3153.27) 3453.83,3150.56 3459.4,3144.99 R77.2@3459.4,3117.69 ; C44.1@3537.87,3118.69 v1@3537.85,3153.25 ; J4.B9@3548.24,2997.07 3548.24,2946.9 R79.2@3557.32,2937.82 ; v1(3559.71,2534.66) 3604.36,2534.66 C45.2@3610.38,2540.69 ; v1(3635.83,2680.27) 3674.19,2680.27 U14.1@3675.01,2681.09
  other v1: 3537.83,3153.27
VDD_1V2: C55.1 C56.1 C57.1 C58.1 C59.1 C60.1 C61.1 C85.2 L5.2 TP7.1 U1.F9 U1.F10 U1.G6 U1.J11 U1.K8 U1.K9 U12.10 | length 567.9
  Top Layer w10: v2(3395.33,2157.28) U1.G6@3411.08,2141.53 ; v2(3458.32,2031.29) U1.K8@3474.07,2047.04 ; U1.K9@3505.57,2047.04 v2(3521.31,2031.29) ; U1.F9@3505.57,2173.03 v2(3521.31,2188.77) ; U1.F10@3537.06,2173.03 v2(3552.81,2188.77) ; U1.J11@3568.56,2078.54 v2(3584.31,2062.79) ; v1(4045.83,3111.27) 4046.69,3110.41 4046.69,3094.13 4046.77,3094.06 U12.10@4047.55,3094.06
  Bottom w10: v1@3780,2383.79 C57.1@3780,2409.38 ; v1(3805.8,2407.06) 3828.38,2407.06 C59.1@3830.04,2408.73 ; C60.1@3880.07,2408.93 3881.73,2407.27 v1(3908.83,2407.27)
  Bottom w12: v2(3458.32,2031.29) v2(3521.31,2031.29) ; C55.1@3491.09,2252.44 3490.54,2251.89 C56.1@3490.54,2195.65 3497.42,2188.77 v2(3521.31,2188.77) v2(3552.81,2188.77) ; v2(3584.31,2062.79) 3584.31,2071.41 C58.1@3607.92,2095.03 ; v1(4097.83,2259.27) 4123.29,2259.27 4129.87,2252.69 L5.2@4203.87,2252.69
  other v1: 3778.83,2377.27
VDDA_3V3: C32.1 C33.1 C62.1 C67.1 C120.1 C124.1 L4.2 U1.N1 U1.T6 U23.2 U24.4 | length 599.4
  Top Layer w12: U24.4@2876.55,1784.77 v1@2928.33,1784.77 ; U23.2@2878.72,1564 2880.94,1566.22 2908.22,1566.22 2928.87,1586.87 v1(2928.87,1624.16) ; v2(3226.54,1953.03) 3227.02,1952.55 U1.N1@3253.6,1952.55 ; v2(3400.09,1832.07) 3401.24,1833.21 3401.24,1847.22 3411.08,1857.05 U1.T6@3411.08,1858.07
  Bottom w12: v1(2929.24,1698.22) 2962.01,1731 C62.1@2964.5,1731 ; v1(2960.24,1625.06) 2960.24,1663.73 C124.1@2964.5,1668 ; v1(2963.24,1827.46) 2963.24,1794.27 C120.1@2963.5,1794 ; C33.1@3166.16,1702.39 3167.09,1702.39 3178.86,1714.16 3178.86,1729.86 3207.09,1758.09 3207.09,1768.65 v1(3209,1770.56) ; C32.1@3173.59,1947.07 3179.56,1953.03 v2(3226.54,1953.03) ; C67.1@3235.66,1703.03 3241.7,1709.07 3241.7,1769.52 v1(3242.74,1770.56) ; L4.2@3304,1723 3317,1736 v1(3317,1770.56) v1@3317,1771
  other v1: 2928.83,1784.27
VDDIO_3V3: C65.1 C68.1 C69.1 C70.1 C71.1 C72.1 C73.1 C74.1 C75.1 C76.1 C77.1 C78.1 C79.1 C80.1 C81.1 C82.1 C83.1 L3.2 TP6.1 U1.B1 U1.E15 U1.G7 U1.G8 U1.G15 U1.H5 U1.J5 U1.J10 U1.K7 U1.K10 U1.R11 U1.T11 U1.T15 | length 1572.9
  Top Layer w5: U1.G15@3694.54,2141.53 3710.29,2157.28 3736.98,2157.28 ; U1.E15@3694.54,2204.52 3710.29,2220.27 v1(3756.69,2220.27)
  Top Layer w6.1: U1.T15@3694.54,1858.07 U1.T15@3695.07,1857.54 ; v2@3695.07,1832.09 v2(3695.59,1831.56)
  Top Layer w10: v2(3363.83,2062.72) 3363.83,2062.79 U1.J5@3379.58,2078.54 ; v2@3363.83,2126.46 v2(3363.83,2125.78) U1.H5@3379.58,2110.03 ; v2(3426.83,2031.29) U1.K7@3442.57,2047.04 ; v2(3426.83,2157.28) U1.G7@3442.57,2141.53 ; v2(3458.32,2157.28) U1.G8@3474.07,2141.53 ; U1.K10@3537.06,2047.04 v2(3552.81,2031.29) ; U1.J10@3537.06,2078.54 v2(3552.81,2062.79)
  Top Layer w12: v1(3203,2303) 3205.71,2303 3209.69,2299.01 U1.B1@3253.6,2299.01 ; v1(3218.83,2355.27) 3219.83,2354.27 v1(3248.83,2354.27) ; U1.R11@3568.56,1889.56 3568.56,1724.3 3579.83,1713.03 v1(3579.83,1712.27) ; v2@3695.07,1832.09 U1.T15@3695.07,1857.54 ; 3736.98,2157.28 3800,2157.28 3855,2102.28 v1@3855,2100
  Bottom w10: C77.1@3330.78,2095.03 3363.08,2062.72 v2(3363.83,2062.72) ; v2(3363.83,2125.78) 3363.83,2118.06 C71.1@3386.97,2094.92 ; v2(3426.83,2157.28) v2(3458.32,2157.28)
  Bottom w12: C72.1@3082.85,2346.14 C74.1@3082.85,2394.82 ; C72.1@3089.62,2341.05 v1(3128.73,2341.05) ; C76.1@3097.66,2297 3106.15,2297 v1(3122.33,2313.18) ; C83.1@3146.62,1859 3151.98,1864.35 3174.65,1864.35 3178.29,1868 v1(3181,1868) ; C68.1@3146.72,1759.77 3152.53,1765.58 3169.87,1765.58 3176.29,1772 v1@3179,1772 ; C75.1@3146.72,1810.07 3150.65,1810.07 3156.46,1815.88 3156.46,1819.81 3175.74,1839.09 v1(3184.09,1839.09) ; v1(3159.71,2344.45) 3170.71,2355.45 C73.1@3170.71,2394.83 ; C79.1@3177.62,2004 3191.62,1990 v2(3226,1990) ; C69.1@3182.72,2094.07 3197.86,2094.07 v2(3213.83,2110.03) ; v1(3218.83,2355.27) 3218.83,2393.69 C81.1@3220.07,2394.93 ; v1(3248.83,2354.27) 3250.74,2356.18 3250.74,2372.67 3269.07,2391 C80.1@3269.07,2394.93 ; C70.1@3551.17,2095.03 3552.81,2093.38 v2(3552.81,2062.79) v2(3552.81,2031.29) ; C78.1@3695.47,1794.07 C82.1@3695.47,1864.07 ; v1(3945,2141) 3982.56,2141 L3.2@3987.87,2135.69 ; C65.1@3992.5,2211 3993.47,2211 4006.17,2223.7 4006.17,2237.17 4020.09,2251.09 4049.09,2251.09 v1(4051,2253)
  other v1: 3179,1770.56 3855.95,2102.21
XDS_CC1: J1.A5 R16.2 U4.4 U4.7 | length 339.5
  Top Layer w6.25: J1.A5@2133.54,3117.53 2297.63,3117.53 2327.09,3088.07 2326.81,3087.78 2326.81,3054.98 U4.7@2326.53,3054.7 U4.4@2326.53,3021.82
  Bottom w5: v1(2325,3089) 2351,3063 R16.2@2351,3032.48
XDS_CC2: J1.B5 R17.1 U4.5 U4.6 | length 685.6
  Top Layer w6.25: U4.5@2346.22,3021.82 U4.6@2346.22,3054.7 2346.22,3074.19 v1@2357.09,3085.07
  Bottom w5: J1.B5@2056.37,3056.5 2030,3030.13 2030,2988 2061,2957 2214,2957 2283.83,3026.83 2283.83,3084.83 2308,3109 2338.97,3109 v1@2360,3087.97 ; v1(2364.1,3086) 2386.04,3086 2415.29,3056.75 2415.29,3038.31 R17.1@2421.1,3032.5
XDS_D_N: J1.A7 J1.B7 U2.93 U4.2 U4.9 | length 687.1
  Top Layer w6.1: J1.B7@2083.93,3103.75 2083.93,3101.73 2105.39,3080.28 2131.42,3080.28 J1.A7@2133.54,3078.16 ; v1@2196.61,2794.35 2199.78,2797.52 2199.78,2806.55 2283.11,2889.89 2283.11,3010.58 2287.16,3014.64 U4.2@2287.16,3021.82 U4.9@2287.16,3054.7 2286.27,3055.58 2286.27,3065.84 2260.01,3092.1 2224.18,3092.1 2222.93,3093.35 2222.73,3093.35 2216.83,3099.25 v1(2212.53,3099.25)
  Bottom w6.1: J1.B7@2083.93,3103.75 2087.55,3103.75 2097.25,3094.05 2162.63,3094.05 2167.83,3099.25 v1(2212.53,3099.25) ; U2.93@2107.7,2782.11 2131.8,2782.11 2133.54,2783.85 2186.1,2783.85 v1@2196.61,2794.35
  other v1: 2197.91,2792.12
XDS_D_P: J1.A6 J1.B6 U2.94 U4.1 U4.10 | length 638.8
  Top Layer w6.1: J1.A6@2133.54,3097.84 2173.16,3097.84 v1(2191,3080) 2255,3080 2266.59,3068.41 2266.59,3055.58 U4.10@2267.48,3054.7 U4.1@2267.48,3021.82 2267.48,3014.64 2271.01,3011.1 2271.01,2894.9 2189.58,2813.47 2179.67,2813.47 v1(2176.63,2810.42)
  Bottom w6.1: J1.B6@2083.93,3072.25 2087.55,3072.25 2097.25,3081.95 2189.05,3081.95 v1(2191,3080) ; U2.94@2107.7,2797.86 2131.8,2797.86 2133.71,2795.95 2164.26,2795.95 2176.63,2808.32 v1(2176.63,2810.42)
XDS_RESET_OUT: U2.40
XDS_RXD: U2.33 U6.6 | length 329.8
  Top Layer w5: v1(2613.69,2421.29) 2613.69,2439.69 2695.7,2521.7 2733.67,2521.7 U6.6@2734.52,2522.56
  Bottom w5: v1(2613.69,2421.29) 2613.69,2405.31 2654.94,2364.06 U2.33@2654.94,2282.11
XDS_TCK_SWDCLK: U2.35 U6.5 | length 375.3
  Top Layer w5: v1(2576,2431) 2692.56,2547.56 U6.5@2734.52,2547.56
  Bottom w5: v1(2576,2431) 2576,2410.27 2623.44,2362.83 U2.35@2623.44,2282.11
XDS_TDI: U2.38 U6.2 | length 488.6
  Top Layer w5: v1(2544,2492) 2543,2493 2543,2525 2640.56,2622.56 U6.2@2734.52,2622.56
  Bottom w5: v1(2544,2492) 2544,2341 2575.65,2309.35 2575.65,2282.66 U2.38@2576.2,2282.11
XDS_TDO_SWO: U2.37 U6.7 | length 308.4
  Top Layer w5: v1(2581.49,2350.51) 2602.86,2371.88 2634,2403.03 2634,2440.01 2691.54,2497.56 U6.7@2734.52,2497.56
  Bottom w5: v1(2581.49,2350.51) 2581.49,2345.91 2591.97,2335.43 U2.37@2591.95,2282.11
XDS_TMS_SWDIO: U2.36 U6.3 | length 436.8
  Top Layer w5: v1(2606,2517) 2609.25,2520.25 2616.44,2520.25 2693.74,2597.56 U6.3@2734.52,2597.56
  Bottom w5: v1(2606,2517) 2558.5,2469.5 2558.5,2399.5 2607.7,2350.3 U2.36@2607.7,2282.11
XDS_TXD: U2.34 U6.4 | length 391.1
  Top Layer w5: v1(2595,2475) 2692.56,2572.56 U6.4@2734.52,2572.56
  Bottom w5: v1(2595,2475) 2595,2404 2639.19,2359.81 U2.34@2639.19,2282.11
pads on no net: B1.7 EC1.4 EC1.13 EC1.16 EC1.29 EC1.32 EC1.41 EC1.43 EC1.44 EC1.66 EC1.113 EC1.114 EC1.115 EC1.116 EC1.117 EC2.136 EC2.171 EC2.172 EC2.173 EC2.174 EC2.175 EC2.176 EC2.177 FID1.1 FID2.1 FID3.1 FID4.1 FID5.1 FID6.1 J1.A2 J1.A3 J1.A8 J1.A10 J1.A11 J1.B2 J1.B3 J1.B8 J1.B10 J1.B11 J3.9 J4.A2 J4.A3 J4.A8 J4.A10 J4.A11 J4.B2 J4.B3 J4.B8 J4.B10 J4.B11 J5.9 J5.ALIGN1 J5.ALIGN2 J6.9 J6.ALIGN1 J6.ALIGN2 S4. U1.G16 U1.H1 U1.J1 U1.J2 U1.K1 U1.K3 U1.K4 U1.L6 U1.N5 U1.N6 U1.N8 U1.P4 U1.P5 U1.P6 U1.P8 U1.R5 U1.R7 U2.1 U2.2 U2.5 U2.6 U2.11 U2.12 U2.13 U2.14 U2.15 U2.18 U2.19 U2.20 U2.21 U2.22 U2.23 U2.24 U2.25 U2.27 U2.29 U2.30 U2.31 U2.32 U2.41 U2.42 U2.43 U2.44 U2.45 U2.46 U2.49 U2.50 U2.53 U2.54 U2.56 U2.57 U2.65 U2.67 U2.71 U2.72 U2.73 U2.74 U2.75 U2.76 U2.77 U2.78 U2.81 U2.82 U2.83 U2.84 U2.85 U2.86 U2.91 U2.92 U2.95 U2.102 U2.103 U2.104 U2.105 U2.106 U2.107 U2.108 U2.109 U2.110 U2.111 U2.112 U2.116 U2.117 U2.118 U2.119 U2.120 U2.121 U2.123 U2.124 U2.125 U2.126 U2.127 U2.128 U4.3@2306.85,3021.82 U4.8@2306.85,3054.7 U5.9@3122,2844 U5.9@3122,2893.61 U7.3 U7.5 U11.6 U13.3@3482.69,2805.13 U13.8@3482.69,2838 U17.3@4634.86,2830.21 U17.8@4667.74,2830.21 U19.3@4631.55,1992.82 U19.8@4664.42,1992.82 U23.1 U23.3 U23.7 U23.8 U24.8 U24.9 U24.16 U25.1 U25.8 U26.1 U26.8

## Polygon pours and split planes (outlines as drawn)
GND on Top Layer "TOP_LAYER_GND_P247" (solid, remove dead copper, pour order 247): 1719.72,2053.27 2676.54,2053.27 2919.72,2296.45 2919.72,3343.27 5870.72,3343.27 5870.72,1402.79 5870.72,1286.79 5827.18,1286.79 5808.28,1267.89 5808.28,1037.81 4833.7,1037.81 4813,1058.51 4813,1511.79 4165.69,1511.79 4169.72,1507.75 4169.72,1366.79 4194.72,1346.79 4233.69,1346.79 4233.69,1277.81 4233.69,1267.89 4233.59,1267.79 4056.77,1267.79 4056.77,1033.81 4055.79,1034.79 3025.72,1034.79 3025.72,1246.64 2992.1,1280.27 2948.2,1280.27 2919.72,1251.79 2919.72,1045.79 2015.72,1045.79 2010.72,1040.79 2010.72,1272.79 1838.72,1272.79 1825.69,1285.83 1825.69,1345.79 1887.72,1345.79 1921.88,1379.95 1921.88,1539.27 1719.72,1539.27
5V0 on Top Layer "TOP_LAYER_5V0_P165" (solid, remove dead copper, pour order 165): 3169.55,2799.7 3169.55,2708.82 3008.88,2708.82 3008.88,2799.7
EMU_3V3 on Top Layer "TOP_LAYER_EMU_3V3_P248" (solid, remove dead copper, pour order 248): 1981,2571 2351,2571 2369,2553 2369,2490.19 1981,2490.19
EMU_5V0 on Top Layer "TOP_LAYER_EMU_5V0_P166" (solid, remove dead copper, pour order 166): 1737.86,2450 1976.14,2450 1976.14,2700.43 2013.22,2725.25 2013.22,2810.69 1906.8,2810.69 1906.8,3010.36 1884.16,3033 1736.85,3033
POWER_SWITCH_OUT on Top Layer "TOP_LAYER_POWER_SWITCH_OUT_P239" (solid, remove dead copper, pour order 239): 2918.6,2984 3056,2984 3056,2709.33 2918.6,2709.33
NetT1_4 on Top Layer "TOP_LAYER_NETT1_4_P167" (solid, remove dead copper, pour order 167): 2402,3254 2573,3254 2589,3238 2589,3188 2578,3177 2485,3177 2449,3213 2448.37,3212.37 2399.63,3212.37 2392,3220 2392,3244
NetT1_6 on Top Layer "TOP_LAYER_NETT1_6_P169" (solid, remove dead copper, pour order 169): 2396,3180 2452,3180 2462,3170 2462,3069 2491,3040 2606,3040 2618,3028 2618,2977 2606.44,2965.44 2415.56,2965.44 2387.74,2993.26 2387.74,3171.74
EMU_5V0 on Top Layer "TOP_LAYER_EMU_5V0_P204" (solid, remove dead copper, pour order 204): 2073,3149 2075,3151 2161,3151 2161,3207 2190,3236 2238,3236 2269,3205 2269,3128 2268,3128 2263,3123 2157,3123 2152,3128 2151.73,3127.73 2100.73,3127.73 2093,3120 2071,3120 2071,3148 2072,3149
EMU_5V0 on Top Layer "TOP_LAYER_EMU_5V0_P170" (solid, remove dead copper, pour order 170): 2081,3062 2241,3062 2257,3046 2257,2982 2242,2967 2176,2967 2162,2981 2162,3027 2159,3030 2158,3029 2070,3029 2070,3051 2072,3053
ISO_Pout_5V0 on Top Layer "TOP_LAYER_ISO_POUT_5V0_P210" (solid, remove dead copper, pour order 210): 3229.83,3332.29 3229.83,2973.27 3093.83,2973.27 3093.83,3332.29
NetD1:A_2 on Top Layer "TOP_LAYER_NETD1:A_2_P211" (solid, remove dead copper, pour order 211): 2920.83,3045.36 3093.83,3045.36 3093.83,2965.27 2920.83,2965.27
NetD2:A_2 on Top Layer "TOP_LAYER_NETD2:A_2_P216" (solid, remove dead copper, pour order 216): 2920.83,3188.27 3010.83,3188.27 3036.83,3221.85 3087.63,3221.85 3087.63,3334.27 2920.83,3334.27
EMU_3V3 on Top Layer "TOP_LAYER_EMU_3V3_P238" (solid, remove dead copper, pour order 238): 1978.78,2721 2162.81,2721 2162.81,2503 1978.78,2503
EMU_GND on Top Layer "Top Layer-EMU_GND" (solid, remove dead copper, pour order 240): 1791.87,2215.69 2174.74,2215.69 2255.52,2314.91 2572.87,2314.91 2572.87,2349.87 2566,2349.87 2566,2416.69 2373.83,2416.69 2373.83,2389.69 1791.87,2389.68
VDDIO_3V3 on Power 4 "POWER_4_VDDIO_3V3_P183" (solid, remove dead copper, pour order 183): 3401.38,2053.23 3431.27,2053.23 3438.09,2046.41 3438.09,2018.55 3403.24,2018.55 3402.93,2018.24
VDD_1V2 on Power 4 "POWER_4_VDD_1V2_P185" (solid, remove dead copper, pour order 185): 3566.81,2076.55 3602.04,2076.55 3605.22,2073.37 3604.97,2073.12 3604.97,2053.47 3603.59,2052.1 3566.92,2052.1
VDDIO_3V3 on Power 4 "POWER_4_VDDIO_3V3_P184" (solid, remove dead copper, pour order 184): 3535.76,2076.55 3566.81,2076.55 3566.81,2047.58 3571.08,2043.31 3571.08,2019.56 3569.68,2018.16 3536,2018.16
VDD_1V2 on Power 4 "POWER_4_VDD_1V2_P187" (solid, remove dead copper, pour order 187): 3439.31,2048.57 3439.57,2048.82 3529.81,2048.82 3529.81,2021.34 3525.4,2016.93 3447.38,2016.93 3440.45,2023.87
VDDIO_3V3 on Power 4 "POWER_4_VDDIO_3V3_P226" (solid, remove dead copper, pour order 226): 3415.99,2173.15 3480.63,2173.15 3480.63,2149.29 3467.21,2135.87 3415.99,2135.87
VDD_1V2 on Power 4 "POWER_4_VDD_1V2_P213" (solid, remove dead copper, pour order 213): 3377.14,2173.27 3410.83,2173.27 3410.83,2139.78 3377.14,2139.78
VDDIO_3V3 on Power 4 "POWER_4_VDDIO_3V3_P243" (solid, remove dead copper, pour order 243): 3062.12,2693 3481,2693 3481,2149.7 3467.17,2135.87 3407.87,2135.87 3407.87,2167.9 3402.07,2173.7 3401.32,2172.94 3371.71,2172.94 3371.71,2109.16 3398.65,2082.22 3420.92,2082.22 3420.92,2041.09 3450.34,2011.67 3529.24,2011.67 3535.77,2018.19 3535.77,2074.66 3566.81,2074.66 3566.81,2047.58 3699.24,2047.58 3712.83,2061.17 3712.83,2236.27 3754.05,2277.48 4031.15,2277.48 4095.99,2212.64 4112.05,2212.64 4124.85,2199.84 4124.85,1807.85 3932.87,1615.87 3080.13,1615.87 3062.12,1635.32
5V0 on Power 4 "POWER_4_5V0_P253" (solid, remove dead copper, pour order 253): 3290.63,3353.27 3292.82,3268 3292.82,3171.58 3156.51,3035.27 3062.29,2941.05 3063.61,2693 3486.33,2693 3486.33,3145.43 3719,3146.12 3719,2962.75 4032.83,2962.75 4032.83,3104.27 4065.9,3137.34 4209.9,3137.34 4213.27,2957.92 5170.57,2950.53 5403.83,2717.27 5403.83,2378.14 5165.94,2378.14 5153.94,1516.27 5866.83,1516.27 5866.83,3340.27 5853.83,3353.27
EMU_5V0 on Power 4 "POWER_4_EMU_5V0_P251" (solid, remove dead copper, pour order 251): 1744.33,3336.27 2621.83,3336.27 2621.83,3061.27 2540.83,2980.27 2231.89,2980.27 1969,2717.38 1969,2470 1935,2436 1766,2436 1746,2456 1746.09,2456.09 1746.09,3333.01
USB_5V0 on Power 4 "POWER_4_USB_5V0_P244" (solid, remove dead copper, pour order 244): 3492,3142.42 3704.33,3142.42 3718.84,3127.91 3716.76,3125.83 3716.76,2567.68 3701.5,2552.42 3492,2552.42
3V3 on Power 4 "POWER_4_3V3_P250" (solid, remove dead copper, pour order 250): 4162,2430 4133.23,2458.77 4133.23,2550.03 4241.24,2658.04 4241,2658.28 4241,2944.11 4271.94,2975.06 5146.04,2975.06 5404.83,2716.27 5404.83,2394.98 5401.27,2394.98 5383.05,2376.77 5188.23,2376.77 5135,2430 4151,2430
1V2 on Power 4 "POWER_4_1V2_P249" (solid, remove dead copper, pour order 249): 4109.83,2412.45 4134.84,2437.46 5127.54,2437.46 5170,2395 5170,1532.33 5152.67,1515 4994,1515 4972.58,1536.42 4972.58,1882.42 4813.15,2041.86 4811.86,2040.56 4144.6,2040.56 4128.24,2056.92 4128.24,2299.76 4109.83,2318.17
VDD_1V2 on Power 4 "POWER_4_VDD_1V2_P245" (solid, remove dead copper, pour order 245): 3365.92,2173.27 3407.6,2173.27 3407.6,2145.83 3478.47,2145.83 3478.47,2567.89 3715.24,2567.89 3715.24,2963.18 4018.71,2963.18 4018.71,3120.97 4046.43,3148.69 4204.73,3148.69 4232.49,3120.93 4232.49,2658.46 4124.48,2550.45 4124.48,2177 4020.38,2177 4020.38,2281.69 3753.96,2281.69 3712.83,2237 3712.83,2047.22 3558.64,2047.22 3558.64,2076.69 3532.92,2076.69 3532.92,2016.72 3433.75,2016.72 3433.75,2073.51 3365.92,2104.15
EMU_3V3 on Power 4 "POWER_4_EMU_3V3_P252" (solid, remove dead copper, pour order 252): 1737.81,3342.27 2773.69,3342.27 2773.69,2363.12 2613.83,2203.27 1732.87,2203.27
HSEC_5V0 on Power 4 "POWER_4_HSEC_5V0_P254" (solid, remove dead copper, pour order 254): 2921.53,3337.58 3293,3338.41 3293,3155.81 3066,2928.81 3066,1623.16 3569.85,1623.16 3694.81,1748.13 4050.7,1748.13 4125.05,1822.48 4125.05,2066.27 4796.39,2066.27 4977.83,1884.83 4977.83,1515.27 5133.83,1515.27 5852.53,1513.16 5860.83,1048.27 5873.83,1061.27 5687.83,1055.27 4835.47,1064.63 4830.83,1488.27 4812.09,1531.29 4180.61,1531.29 4229.53,1298.53 4050.7,1295.49 4053.83,1040.78 3148.32,1040.78 3180.83,1040.78 1738.83,1040.78 1738.83,2054.27 1813.83,2054.27 2675.53,2054.27 2921.53,2300.26
GND on Bottom "BOTTOM_GND_P235" (solid, remove dead copper, pour order 235): 1719.72,2053.27 2676.54,2053.27 2919.72,2296.45 2919.72,3343.27 5870.72,3343.27 5870.72,1402.79 5870.72,1286.79 5827.18,1286.79 5808.28,1267.89 5808.28,1058.51 4813,1058.51 4813,1511.79 4165.69,1511.79 4169.72,1507.75 4169.72,1366.79 4194.72,1346.79 4233.69,1346.79 4233.69,1277.81 4233.69,1267.89 4233.59,1267.79 4056.77,1267.79 4056.77,1033.81 4055.79,1034.79 3025.72,1034.79 3025.72,1246.64 2992.1,1280.27 2948.2,1280.27 2919.72,1251.79 2919.72,1045.79 2015.72,1045.79 2010.72,1040.79 2010.72,1272.79 1838.72,1272.79 1838.72,1345.79 1887.72,1345.79 1921.88,1379.95 1921.88,1539.27 1719.72,1539.27
EMU_3V3 on Bottom "BOTTOM_EMU_3V3_P234" (solid, remove dead copper, pour order 234): 2078,2695 2078,2529.55 1959,2529.55 1959,2695
NetC48_2 on Bottom "BOTTOM_NETC48_2_P219" (solid, remove dead copper, pour order 219): 5103.84,1777.69 5154.64,1777.69 5154.64,1765.59 5186.29,1733.95 5294.59,1733.95 5294.59,1678.24 5300.33,1674.64 5522.04,1674.87 5522.04,1715.48 5523.97,1717.4 5594.81,1717.4 5594.81,1679.48 5589.97,1674.64 5550.44,1674.64 5550.44,1587.99 5551.33,1587.1 5545.27,1581.04 5297.83,1581.04 5285.44,1593.44 5285.44,1630.2 5272.64,1643 5126,1643 5103.84,1665.16
NetC50_2 on Bottom "BOTTOM_NETC50_2_P203" (solid, remove dead copper, pour order 203): 5110,2069.34 5110,2013.68 5140.32,2013.68 5189.18,1964.82 5295.41,1964.82 5295.41,2025 5546,2025 5546,2058.05 5550.44,2062.5 5591.94,2062.5 5591.94,2028.87 5599.66,2028.87 5639.18,2028.87 5639.18,2106.82 5626,2120 5295.41,2120 5295.41,2054.66 5198.34,2054.66 5183.66,2069.34
NetL2_1 on Bottom "BOTTOM_NETL2_1_P194" (solid, remove dead copper, pour order 194): 5480,1940 5434.75,1940 5404.44,1909.69 5404.44,1871.16 5383.69,1871.16 5383.69,1930.43 5356.12,1958 5301,1958 5301,2026 5480,2026
NetL1_1 on Bottom "BOTTOM_NETL1_1_P222" (solid, remove dead copper, pour order 222): 5361.76,1744.71 5386,1768.96 5386,1828 5397.51,1828 5397.76,1828.24 5402.57,1823.43 5402.57,1806.29 5456.86,1752 5484,1752 5484,1683 5361.76,1683
5V0 on Bottom "BOTTOM_5V0_P225" (solid, remove dead copper, pour order 225): 5183.99,1801.23 5183.99,1844.5 5244,1844.5 5244,1820.73 5353.46,1820.73 5381.67,1820.73 5381.67,1764.63 5356.18,1739.14 5183.99,1739.14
